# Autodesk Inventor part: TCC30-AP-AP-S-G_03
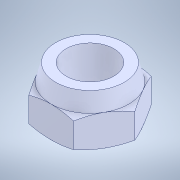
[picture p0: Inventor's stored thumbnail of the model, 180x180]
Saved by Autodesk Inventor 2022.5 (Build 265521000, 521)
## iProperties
Created: 2023-09
Part Number: TCC30-AP-AP-S-G_03
Material: 一般
Document SubType Name: Modeling
Designer: ImaoCorp
Density: 1 g/cm^3
Appearance: 既定
Author: ImaoCorp
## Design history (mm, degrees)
feature "TCC30-AP-AP-S-G_03"
node "ソリッド1"
